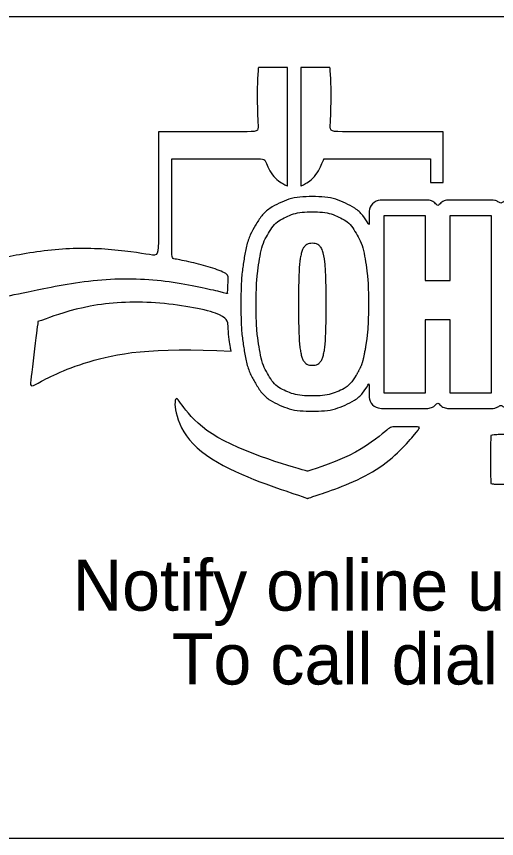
# Model space of a CAD drawing. Extents: x 0 to 40.2, y 0 to 22.
# Drawn here: x 2.292 to 3.61, y 2.15 to 4.404 of the extents above; entities that cross this region are included whole.
import ezdxf

# ---------------------------------------------------------------- set-up
doc = ezdxf.new("R2010")
doc.units = 0
doc.layers.add('SH_Data', color=7, linetype='Continuous')
doc.layers.add('SH_Text', color=7, linetype='Continuous')

msp = doc.modelspace()

# ---------------------------------------------------------------- linework, layer by layer
at = {"layer": 'SH_Data'}
msp.add_lwpolyline([(1.9992, 4.4045), (6.8508, 4.4045), (6.8508, 2.15), (1.9992, 2.15)], close=True, dxfattribs=at)
at = {"layer": 'SH_Text'}
for points, degree in [([(2.8714, 3.6451), (2.8714, 3.6451), (2.8713, 3.6451), (2.8713, 3.6451), (2.7035, 3.6848), (2.5151, 3.6887), (2.3198, 3.6488), (2.2463, 3.6337), (2.1755, 3.613), (2.1076, 3.5876), (2.1114, 3.6278), (2.1154, 3.6704), (2.1192, 3.7105), (2.1512, 3.7194), (2.1834, 3.7277), (2.2164, 3.7345), (2.3789, 3.7677), (2.5364, 3.7705), (2.6813, 3.7475), (2.6813, 3.7475), (2.6813, 4.0883), (2.6813, 4.0883), (2.6813, 4.0883), (2.9557, 4.0883), (2.9557, 4.0883), (2.9507, 4.1972), (2.9557, 4.2641), (2.9557, 4.2641), (2.9557, 4.2641), (3.0355, 4.2641), (3.0355, 4.2641), (3.0355, 4.2641), (3.0355, 3.9394), (3.0355, 3.9394), (3.0355, 3.9394), (2.9956, 3.96), (2.9721, 4.0141), (2.9721, 4.0141), (2.7181, 4.0141), (2.7181, 4.0141), (2.7181, 4.0141), (2.7181, 3.741), (2.7181, 3.741), (2.7723, 3.7307), (2.8247, 3.7167), (2.8747, 3.6992), (2.873, 3.6825), (2.872, 3.6646), (2.8714, 3.6451)], 3), ([(3.1358, 4.0142), (3.1358, 4.0142), (3.1359, 4.0142), (3.1359, 4.0142), (3.1125, 3.9602), (3.0726, 3.9395), (3.0726, 3.9395), (3.0726, 3.9395), (3.0726, 4.2641), (3.0726, 4.2641), (3.0726, 4.2641), (3.1523, 4.2641), (3.1523, 4.2641), (3.1523, 4.2641), (3.1573, 4.1972), (3.1523, 4.0883), (3.1523, 4.0883), (3.4633, 4.0883), (3.4633, 4.0883), (3.4633, 4.0883), (3.4633, 3.9487), (3.4633, 3.9487), (3.4633, 3.9487), (3.4285, 3.9487), (3.4285, 3.9487), (3.4285, 3.9487), (3.4285, 4.0142), (3.4285, 4.0142), (3.4285, 4.0142), (3.1358, 4.0142), (3.1358, 4.0142)], 3), ([(4.453, 3.8646), (4.4213, 3.8951), (4.3771, 3.9098), (4.318, 3.9098), (4.2071, 3.9098), (4.1436, 3.854), (4.1375, 3.7525), (4.1311, 3.7837), (4.1218, 3.8097), (4.1088, 3.8314), (4.0924, 3.8589), (4.0703, 3.8793), (4.043, 3.8922), (4.0177, 3.9042), (3.9873, 3.9103), (3.9525, 3.9103), (3.9177, 3.9103), (3.8873, 3.9042), (3.8621, 3.8922), (3.8373, 3.8805), (3.8171, 3.8623), (3.8012, 3.8386), (3.8012, 3.8386), (3.8012, 3.8587), (3.8012, 3.8587), (3.8012, 3.8819), (3.7824, 3.9007), (3.7592, 3.9007), (3.7592, 3.9007), (3.6469, 3.9007), (3.6469, 3.9007), (3.637, 3.9007), (3.6282, 3.8967), (3.6209, 3.8909), (3.6137, 3.8967), (3.6049, 3.9007), (3.5949, 3.9007), (3.5949, 3.9007), (3.4826, 3.9007), (3.4826, 3.9007), (3.4684, 3.9007), (3.4559, 3.8937), (3.4482, 3.8828), (3.4406, 3.8937), (3.4281, 3.9007), (3.4138, 3.9007), (3.4138, 3.9007), (3.3016, 3.9007), (3.3016, 3.9007), (3.2784, 3.9007), (3.2595, 3.882), (3.2595, 3.8587), (3.2595, 3.8587), (3.2595, 3.8325), (3.2595, 3.8325), (3.2432, 3.8594), (3.2214, 3.8795), (3.1945, 3.8922), (3.1692, 3.9042), (3.1388, 3.9103), (3.104, 3.9103), (3.0692, 3.9103), (3.0388, 3.9042), (3.0136, 3.8922), (2.9862, 3.8793), (2.9641, 3.8589), (2.9477, 3.8314), (2.9329, 3.8067), (2.9224, 3.7753), (2.9163, 3.7382), (2.9108, 3.704), (2.9079, 3.6626), (2.9079, 3.6152), (2.9079, 3.5678), (2.9108, 3.5263), (2.9163, 3.4921), (2.9224, 3.455), (2.9329, 3.4236), (2.9477, 3.3989), (2.9643, 3.3711), (2.9869, 3.3507), (3.0145, 3.3386), (3.0395, 3.3277), (3.0696, 3.3221), (3.1039, 3.3221), (3.1382, 3.3221), (3.1683, 3.3277), (3.1932, 3.3386), (3.2206, 3.3506), (3.2428, 3.3706), (3.2594, 3.3978), (3.2594, 3.3978), (3.2594, 3.3716), (3.2594, 3.3716), (3.2594, 3.3485), (3.2783, 3.3296), (3.3015, 3.3296), (3.3015, 3.3296), (3.4138, 3.3296), (3.4138, 3.3296), (3.428, 3.3296), (3.4405, 3.3367), (3.4481, 3.3475), (3.4558, 3.3367), (3.4683, 3.3296), (3.4825, 3.3296), (3.4825, 3.3296), (3.5948, 3.3296), (3.5948, 3.3296), (3.6048, 3.3296), (3.6136, 3.3336), (3.6208, 3.3394), (3.6281, 3.3336), (3.6369, 3.3296), (3.6468, 3.3296), (3.6468, 3.3296), (3.7591, 3.3296), (3.7591, 3.3296), (3.7823, 3.3296), (3.8011, 3.3484), (3.8011, 3.3716), (3.8011, 3.3716), (3.8011, 3.3918), (3.8011, 3.3918), (3.8172, 3.3677), (3.8379, 3.3497), (3.8631, 3.3386), (3.888, 3.3277), (3.9181, 3.3221), (3.9524, 3.3221), (3.9867, 3.3221), (4.0168, 3.3277), (4.0417, 3.3386), (4.0695, 3.3507), (4.0921, 3.3711), (4.1086, 3.3988), (4.1193, 3.4168), (4.1276, 3.4377), (4.1338, 3.462), (4.139, 3.4218), (4.154, 3.3892), (4.179, 3.3652), (4.2113, 3.3341), (4.2566, 3.3191), (4.3178, 3.3191), (4.4037, 3.3191), (4.4613, 3.352), (4.4871, 3.4125), (4.4871, 3.4125), (4.4956, 3.4125), (4.4956, 3.4125), (4.4956, 3.4125), (4.4956, 3.3651), (4.4956, 3.3651), (4.4956, 3.3427), (4.5137, 3.3245), (4.5361, 3.3245), (4.5361, 3.3245), (4.6599, 3.3245), (4.6599, 3.3245), (4.6823, 3.3245), (4.7005, 3.3427), (4.7005, 3.3651), (4.7005, 3.3651), (4.7005, 3.6372), (4.7005, 3.6372), (4.7019, 3.6372), (4.7031, 3.637), (4.7045, 3.637), (4.7045, 3.637), (4.7045, 3.3651), (4.7045, 3.3651), (4.7045, 3.3427), (4.7227, 3.3245), (4.745, 3.3245), (4.745, 3.3245), (4.8689, 3.3245), (4.8689, 3.3245), (4.8837, 3.3245), (4.8966, 3.3326), (4.9037, 3.3446), (4.9094, 3.3367), (4.9187, 3.3315), (4.9293, 3.3315), (4.9293, 3.3315), (4.9996, 3.3315), (4.9996, 3.3315), (5.0172, 3.3315), (5.0315, 3.3457), (5.0315, 3.3633), (5.0315, 3.3633), (5.0315, 3.3918), (5.0315, 3.3918), (5.0328, 3.3884), (5.0338, 3.3849), (5.0355, 3.3818), (5.045, 3.3639), (5.0591, 3.3499), (5.0777, 3.3401), (5.0954, 3.3308), (5.1174, 3.3262), (5.1449, 3.3262), (5.1725, 3.3262), (5.1943, 3.3314), (5.2119, 3.3416), (5.2292, 3.3517), (5.2426, 3.3656), (5.252, 3.3827), (5.252, 3.3827), (5.252, 3.3633), (5.252, 3.3633), (5.252, 3.3457), (5.2663, 3.3315), (5.2839, 3.3315), (5.2839, 3.3315), (5.3593, 3.3315), (5.3593, 3.3315), (5.3769, 3.3315), (5.3912, 3.3457), (5.3912, 3.3633), (5.3912, 3.3633), (5.3912, 3.503), (5.3912, 3.503), (5.3912, 3.511), (5.3923, 3.5146), (5.3921, 3.515), (5.3936, 3.5159), (5.4002, 3.517), (5.4075, 3.5163), (5.4098, 3.5161), (5.412, 3.5157), (5.4145, 3.5153), (5.416, 3.515), (5.4175, 3.5155), (5.4191, 3.5154), (5.4189, 3.5092), (5.4184, 3.5037), (5.4184, 3.4969), (5.4184, 3.4675), (5.4207, 3.4439), (5.4254, 3.4247), (5.4301, 3.4055), (5.4363, 3.3902), (5.4442, 3.3781), (5.4411, 3.3765), (5.4384, 3.3745), (5.436, 3.372), (5.43, 3.366), (5.4267, 3.3577), (5.4269, 3.3492), (5.4272, 3.33), (5.4308, 3.3134), (5.4375, 3.2999), (5.4446, 3.2856), (5.4545, 3.2741), (5.4671, 3.2655), (5.4787, 3.2578), (5.492, 3.2524), (5.5067, 3.2496), (5.5192, 3.2471), (5.5327, 3.2459), (5.5468, 3.2459), (5.5628, 3.2459), (5.5781, 3.2477), (5.5922, 3.2514), (5.6082, 3.2556), (5.6222, 3.2627), (5.6341, 3.2724), (5.6468, 3.2826), (5.6566, 3.2962), (5.6636, 3.3127), (5.6701, 3.3283), (5.6734, 3.3467), (5.6734, 3.3676), (5.6734, 3.3676), (5.6734, 3.6196), (5.6734, 3.6196), (5.6734, 3.6372), (5.6592, 3.6514), (5.6416, 3.6514), (5.6416, 3.6514), (5.6416, 3.6513), (5.6416, 3.6513)], 3), ([(3.224, 3.4204), (3.2119, 3.4002), (3.196, 3.3857), (3.1763, 3.3771), (3.1565, 3.3685), (3.1324, 3.3641), (3.1038, 3.3641), (3.0751, 3.3641), (3.051, 3.3684), (3.0314, 3.3771), (3.0116, 3.3857), (2.9958, 3.4002), (2.9837, 3.4204), (2.9715, 3.4406), (2.9629, 3.4668), (2.9577, 3.4989), (2.9524, 3.5309), (2.9499, 3.5697), (2.9499, 3.6152), (2.9499, 3.6606), (2.9525, 3.6994), (2.9577, 3.7315), (2.9629, 3.7635), (2.9715, 3.7897), (2.9837, 3.8099), (2.9958, 3.8302), (3.0116, 3.8449), (3.0314, 3.8543), (3.0511, 3.8637), (3.0752, 3.8683), (3.1038, 3.8683), (3.1323, 3.8683), (3.1565, 3.8636), (3.1763, 3.8543), (3.196, 3.845), (3.2119, 3.8302), (3.224, 3.8099), (3.2361, 3.7897), (3.2447, 3.7635), (3.25, 3.7315), (3.2551, 3.6994), (3.2578, 3.6606), (3.2578, 3.6152), (3.2578, 3.5697), (3.2551, 3.5309), (3.25, 3.4989)], 3), ([(3.4825, 3.3716), (3.4825, 3.3716), (3.4825, 3.5723), (3.4825, 3.5723), (3.4825, 3.5723), (3.4137, 3.5723), (3.4137, 3.5723), (3.4137, 3.5723), (3.4137, 3.3716), (3.4137, 3.3716), (3.4137, 3.3716), (3.3014, 3.3716), (3.3014, 3.3716), (3.3014, 3.3716), (3.3014, 3.8588), (3.3014, 3.8588), (3.3014, 3.8588), (3.4137, 3.8588), (3.4137, 3.8588), (3.4137, 3.8588), (3.4137, 3.6801), (3.4137, 3.6801), (3.4137, 3.6801), (3.4825, 3.6801), (3.4825, 3.6801), (3.4825, 3.6801), (3.4825, 3.8588), (3.4825, 3.8588), (3.4825, 3.8588), (3.5947, 3.8588), (3.5947, 3.8588), (3.5947, 3.8588), (3.5947, 3.3716), (3.5947, 3.3716)], 3), ([(3.1355, 3.7482), (3.1381, 3.7355), (3.1398, 3.7183), (3.1406, 3.6967), (3.1414, 3.6751), (3.1418, 3.6479), (3.1418, 3.6152), (3.1418, 3.5824), (3.1414, 3.5553), (3.1406, 3.5337), (3.1398, 3.5121), (3.1382, 3.4949), (3.1355, 3.4822), (3.1329, 3.4695), (3.1291, 3.4606), (3.1241, 3.4556), (3.1191, 3.4506), (3.1124, 3.4481), (3.1039, 3.4481), (3.0954, 3.4481), (3.0887, 3.4506), (3.0836, 3.4556), (3.0787, 3.4606), (3.0748, 3.4695), (3.0722, 3.4822), (3.0697, 3.4949), (3.0679, 3.5121), (3.0671, 3.5337), (3.0663, 3.5553), (3.0659, 3.5824), (3.0659, 3.6152), (3.0659, 3.6479), (3.0663, 3.6751), (3.0671, 3.6967), (3.0679, 3.7183), (3.0696, 3.7355), (3.0722, 3.7482), (3.0747, 3.7609), (3.0786, 3.7698), (3.0836, 3.7748), (3.0887, 3.7797), (3.0954, 3.7823), (3.1039, 3.7823), (3.1124, 3.7823), (3.119, 3.7797), (3.1241, 3.7748), (3.1291, 3.7698), (3.1329, 3.7609), (3.1355, 3.7482)], 3), ([(2.8813, 3.4864), (2.6621, 3.4989), (2.4642, 3.4602), (2.3287, 3.387), (2.3287, 3.387), (2.3506, 3.5655), (2.3506, 3.5655), (2.3506, 3.5655), (2.3506, 3.5676), (2.3506, 3.5676), (2.4859, 3.6161), (2.6712, 3.6267), (2.8713, 3.5905), (2.8722, 3.5556), (2.8745, 3.5249), (2.8788, 3.4988), (2.8795, 3.4945), (2.8804, 3.4905), (2.8813, 3.4864)], 3), ([(3.25, 3.4989), (3.2447, 3.4668), (3.2361, 3.4406), (3.224, 3.4204)], 2), ([(3.0913, 3.1573), (3.0913, 3.1573), (3.2205, 3.197), (3.319, 3.2789), (3.319, 3.2789), (3.4016, 3.2789), (3.4016, 3.2789), (3.2958, 3.1523), (3.0911, 3.0827), (3.0911, 3.0827), (3.0911, 3.0827), (2.729, 3.2059), (2.7188, 3.4226), (2.7751, 3.2403), (3.0913, 3.1573), (3.0913, 3.1573)], 3), ([(3.5947, 3.3716), (3.5947, 3.3716), (3.4825, 3.3716), (3.4825, 3.3716)], 2), ([(3.6676, 3.1955), (3.6831, 3.2011), (3.6902, 3.2123), (3.6902, 3.2243), (3.6902, 3.2363), (3.6833, 3.2456), (3.6738, 3.2506), (3.6638, 3.2563), (3.6522, 3.2582), (3.6333, 3.2582), (3.6179, 3.2582), (3.6014, 3.257), (3.5933, 3.2553), (3.5933, 3.2553), (3.5933, 3.1234), (3.5933, 3.1234), (3.6002, 3.1224), (3.6115, 3.1215), (3.6268, 3.1215), (3.6541, 3.1215), (3.6708, 3.1259), (3.6807, 3.1336), (3.6892, 3.1403), (3.6949, 3.1499), (3.6949, 3.1621), (3.6949, 3.1795), (3.6833, 3.191), (3.6676, 3.1952)], 3)]:
    msp.add_open_spline(points, degree=degree, dxfattribs=at)

# ---------------------------------------------------------------- texts
at = {"layer": 'SH_Data'}
for s, p in [('Notify online using ', (2.4466, 2.775)), ('To call dial 8-1-1 or 800-362-2764', (2.718, 2.5725))]:
    msp.add_text(s, height=0.14, dxfattribs=at).set_placement(p)

doc.saveas('drawing.dxf')
